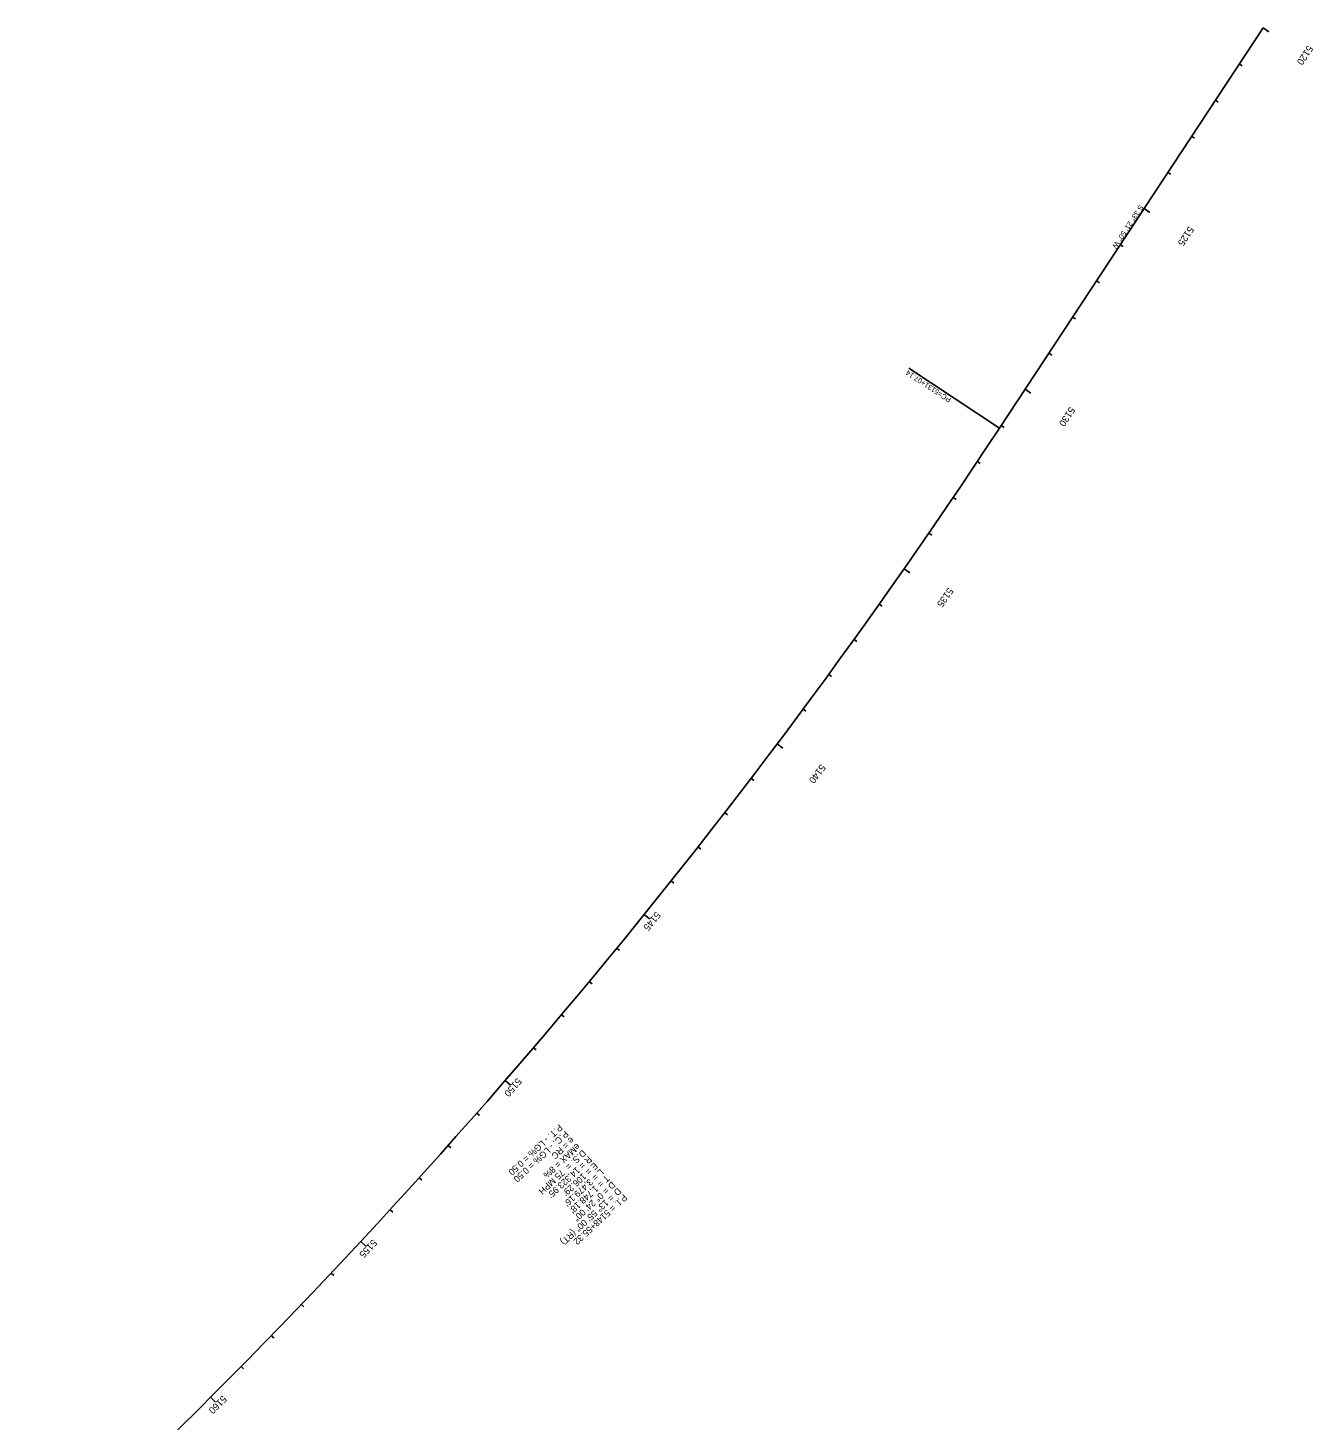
# Model space of a CAD drawing. Extents: x 2160876 to 2175625, y 601634 to 617693.
# Drawn here: x 2172654 to 2175625, y 614476 to 617693 of the extents above; entities that cross this region are included whole.
import ezdxf

# ---------------------------------------------------------------- set-up
doc = ezdxf.new("R2010")
doc.units = 0
for name, color, linetype in [('RD_HC_Cl', 7, 'Continuous'), ('RD_HC_Data', 7, 'Continuous'), ('RD_HC_Data_Tic', 7, 'Continuous'), ('RD_HC_TX_Sta50', 7, 'Continuous')]:
    doc.layers.add(name, color=color, linetype=linetype)

msp = doc.modelspace()

# ---------------------------------------------------------------- linework, layer by layer
at = {"layer": 'RD_HC_Cl'}
msp.add_line((2175508.7, 617693), (2174899.8, 616768.4), dxfattribs=at)
msp.add_arc((2162936.5, 624645.9), 14323.9, 312.71947, 326.63611, dxfattribs=at)
at = {"layer": 'RD_HC_Data'}
msp.add_line((2174899.8, 616768.4), (2174690.3, 616906.3), dxfattribs=at)
at = {"layer": 'RD_HC_Data_Tic'}
for p, q in [((2175508.7, 617693), (2175522.1, 617684.2)), ((2175453.7, 617609.5), (2175460.4, 617605.1)), ((2175398.7, 617526), (2175405.4, 617521.6)), ((2175343.7, 617442.5), (2175350.4, 617438.1)), ((2175288.7, 617359), (2175295.4, 617354.6)), ((2175233.7, 617275.4), (2175247.1, 617266.6)), ((2175178.7, 617191.9), (2175185.4, 617187.5)), ((2175123.7, 617108.4), (2175130.4, 617104)), ((2175068.7, 617024.9), (2175075.4, 617020.5)), ((2175013.7, 616941.4), (2175020.4, 616937)), ((2174958.7, 616857.8), (2174972.1, 616849)), ((2174903.7, 616774.3), (2174910.4, 616769.9)), ((2174848.5, 616691), (2174855.1, 616686.5)), ((2174792.7, 616608), (2174799.3, 616603.5)), ((2174736.3, 616525.4), (2174742.9, 616520.9)), ((2174679.3, 616443.2), (2174692.4, 616434.1)), ((2174621.7, 616361.5), (2174628.3, 616356.8)), ((2174563.6, 616280.1), (2174570.1, 616275.4)), ((2174504.9, 616199.1), (2174511.4, 616194.4)), ((2174445.7, 616118.6), (2174452.1, 616113.8)), ((2174385.9, 616038.4), (2174398.7, 616028.8)), ((2174325.5, 615958.7), (2174331.9, 615953.9)), ((2174264.6, 615879.4), (2174270.9, 615874.5)), ((2174203.1, 615800.5), (2174209.4, 615795.6)), ((2174141.1, 615722.1), (2174147.3, 615717.1)), ((2174078.5, 615644.1), (2174090.9, 615634)), ((2174015.4, 615566.5), (2174021.6, 615561.5)), ((2173951.7, 615489.4), (2173957.9, 615484.3)), ((2173887.5, 615412.7), (2173893.6, 615407.6)), ((2173822.8, 615336.5), (2173828.9, 615331.3)), ((2173757.5, 615260.7), (2173769.6, 615250.2)), ((2173691.8, 615185.4), (2173697.8, 615180.1)), ((2173625.5, 615110.6), (2173631.4, 615105.2)), ((2173558.6, 615036.2), (2173564.6, 615030.8)), ((2173491.3, 614962.2), (2173497.2, 614956.8)), ((2173423.4, 614888.8), (2173435.1, 614877.9)), ((2173355, 614815.8), (2173360.9, 614810.3)), ((2173286.2, 614743.3), (2173291.9, 614737.8)), ((2173216.8, 614671.3), (2173222.5, 614665.7)), ((2173146.9, 614599.8), (2173152.6, 614594.2)), ((2173076.5, 614528.8), (2173087.8, 614517.4))]:
    msp.add_line(p, q, dxfattribs=at)

# ---------------------------------------------------------------- texts
at = {"layer": 'RD_HC_Data'}
for s, height, rotation, p in [('S 33° 21\' 50" W', 12, 236.6361, (2175223.4, 617285.2)), ('PC=5131+07.14', 12, 146.6361, (2174789, 616836.5)), ('P.T. - LG% = 0.50', 15, 222.7195, (2173881.6, 615160.7)), ('P.C. - LG% = 0.50', 15, 222.7195, (2173895.1, 615146)), ('eMAX = 8%', 15, 222.7195, (2173922.3, 615116.6)), ('e = RC', 15, 222.7195, (2173908.7, 615131.3)), ('D.S. =  75 MPH', 15, 222.7195, (2173935.9, 615101.9)), ("R = 14,323.95'", 15, 222.7195, (2173949.4, 615087.2)), ("E = 106.29'", 15, 222.7195, (2173963, 615072.5)), ("L = 3,479.16'", 15, 222.7195, (2173976.6, 615057.8)), ("T = 1,748.18'", 15, 222.7195, (2173990.1, 615043.1)), ('D = 0° 24\' 00"', 15, 222.7195, (2174003.7, 615028.5)), ('D', 15, 222.7195, (2174017.3, 615013.8)), ('    = 13° 55\' 00" (RT)', 15, 222.7195, (2174017.3, 615013.8)), ('P.I. = 5148+55.32', 15, 222.7195, (2174030.8, 614999.1))]:
    msp.add_text(s, height=height, rotation=rotation, dxfattribs=at).set_placement(p)
at = {"layer": 'RD_HC_TX_Sta50'}
for s, rotation, p in [('5120', 236.6361, (2175612.2, 617653.8)), ('5125', 236.6361, (2175336.9, 617235.8)), ('5130', 236.6361, (2175062.2, 616818.6)), ('5135', 235.0647, (2174781.4, 616400.8)), ('5140', 233.0647, (2174486.7, 615992.8)), ('5145', 231.0647, (2174105.6, 615652.1)), ('5150', 229.0647, (2173784.9, 615267.9)), ('5155', 227.0647, (2173451, 614894.9)), ('5160', 225.0647, (2173104.3, 614534))]:
    msp.add_text(s, height=16, rotation=rotation, dxfattribs=at).set_placement(p)

doc.saveas('drawing.dxf')
